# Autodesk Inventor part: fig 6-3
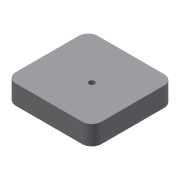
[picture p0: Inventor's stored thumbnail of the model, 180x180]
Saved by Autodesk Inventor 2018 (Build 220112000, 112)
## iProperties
Created: 2004-05
Part Number: fig 6-3
Document SubType Name: Modeling
Designer: CADCIM Technologies
Manufacturer: Standard
Standards Organization: Custom
Density: 1 g/cm^3
Material: Generic
Appearance: Default
Author: CADCIM Technologies
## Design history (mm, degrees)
sketch "Sketch1"
  geometry: L1 (0, 0)-(44.293, 0); L2 (44.293, 0)-(44.293, 42.442); L3 (44.293, 42.442)-(0, 42.442); L4 (0, 42.442)-(0, 0)
  constraints: 8 end point, 2 parallel, 1 horizontal, 1 perpendicular
extrude "Extrusion1" new body sketch "Sketch1" distance "d0" = 10; taper "d1" = 0 deg
fillet "Fillet1" dims "d2" = 5
hole "Hole1" diameter "d6" = 3; stored, may be unused: countersink angle "d10" = 90 deg, drill point angle "d12" = 118 deg; dims "d4" = 20, "d5" = 20, "d7" = 6, "d8" = 4, "d9" = 2, "d11" = 8
body "Solid1"
